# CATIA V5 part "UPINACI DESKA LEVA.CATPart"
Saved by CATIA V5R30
Part number: UPINACI DESKA LEVA
Bounding box of the stored display mesh (mm): x 0 to 36, y -273 to 273, z -173 to 173
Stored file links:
  C:\Users\ondra\Desktop\PŘÍLOHA P III\CATIA\UPINACI DESKA LEVA.CATPart
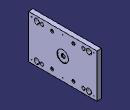
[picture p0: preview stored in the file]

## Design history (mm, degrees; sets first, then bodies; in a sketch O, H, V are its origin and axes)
Set1
  DatumSurface1 to DatumSurface37 "K12/346x"
  Plane1: type Offset, RefPlane yz-plane, Offset 36
  Plane2: type Offset, RefPlane yz-plane, Offset 36
  Sketch1 on Plane2, origin (36, 0, 0), H (0, 1, 0), V (0, 0, 1)
    point P2 (-248, -148)
    point P3 (0, -148)
    point P6 (0, 148)
    construction line L1 (-248, 148) -> (248, 148)
    construction line L2 (248, -148) -> (248, 148)
    construction line L3 (248, -148) -> (-248, -148)
    reference projected line E1 (273, 173) -> (-273, 173) from edge of DatumSurface37
    construction line L4 (0, 148) -> (0, -148)
    reference projected line E2 (273, -173) -> (-273, -173) from edge of DatumSurface33
    reference projected line E3 (273, 173) -> (273, -173) from edge of DatumSurface36
    construction line L5 (-248, -148) -> (-248, 148)
    reference projected line E4 (-273, -173) -> (-273, 173) from edge of DatumSurface34
    distance L1 E1 = 25
    distance L3 E2 = 25
    distance L2 E3 = 25
    distance L5 E4 = 25
    horizontal: L1 H, L3 H
    vertical: L2 V, L4 V, L5 V
    coincidence: P6 L1, L3 P3, L4 O
  Join1: Elements (DatumSurface1; DatumSurface2; DatumSurface3; DatumSurface4; DatumSurface5; DatumSurface6; DatumSurface7; DatumSurface8; DatumSurface9; DatumSurface10; DatumSurface11; DatumSurface12; DatumSurface13; DatumSurface14; DatumSurface15; DatumSurface16; DatumSurface17; DatumSurface18; DatumSurface19; DatumSurface20; DatumSurface21; DatumSurface22; DatumSurface23; DatumSurface24; DatumSurface25; DatumSurface26; DatumSurface27; DatumSurface28; DatumSurface29; DatumSurface30; DatumSurface31; DatumSurface32; DatumSurface33; DatumSurface34; DatumSurface35; DatumSurface36; DatumSurface37)
Body1 (main body)
  CloseSurface1: CloseElement Join1
  Sketch2 on {plane type Tangent, Support face of CloseSurface1, RefPoint Sketch1.P2}, origin (36, -248, -148), H (0, 1, 0), V (0, 0, -1)
    point P1 (0, 0)
    reference projected point E1 (0, 0) from Sketch1.P2
    coincidence: E1 P1
  Hole1: placed by Sketch2, at (36, -248, -148) direction (-1, 0, 0), diameter 4.917, depth 8, V-bottom angle 120, threaded "M6", thread diameter 6, thread depth 7, pitch 1
  UserPattern1: of Hole1, copies 6, at the points of Sketch1
  DatumPoint1
  Plane3: type Offset, RefPlane yz-plane, Offset 15
  Sketch3 on {plane type Tangent, Support face of CloseSurface1, RefPoint vertex of DatumPoint1}, origin (-3, -85, -130), H (0, 1, 0), V (0, 0, -1)
    point P1 (0, 0)
    reference projected point E1 (0, 0) from vertex of DatumPoint1
    coincidence: E1 P1
  Hole2: placed by Sketch3, at (36, -85, -130) direction (-1, 0, 0), diameter 20, through (limit type 6), counterbore diameter 24, counterbore depth 8
  DatumPoint2
  Sketch4, origin (-3, 0, 0), H (0, 1, 0), V (0, 0, -1), geometry linked from another document
  UserPattern2: of Hole2, copies 4, at the points of Sketch4
  Sketch5 on {plane type Tangent, Support face of CloseSurface1, RefPoint vertex of DatumPoint2}, origin (44.5, -39, 0), H (0, 1, 0), V (0, 0, -1)
    point P1 (0, 0)
    reference projected point E1 (0, 0) from vertex of DatumPoint2
    coincidence: E1 P1
  Hole3: placed by Sketch5, at (32, -39, 0) direction (-1, 0, 0), diameter 4.134, depth 15, V-bottom angle 120, threaded "M5", thread diameter 5, thread depth 13, pitch 0.8
  DatumPoint3
  Sketch6, origin (44.5, 0, 0), H (0, 0, -1), V (0, 1, 0), geometry linked from another document
  UserPattern3: of Hole3, copies 3, at the points of Sketch6
  Sketch7 on {plane type Tangent, Support face of CloseSurface1, RefPoint vertex of DatumPoint3}, origin (44, 0, 0), H (0, 1, 0), V (0, 0, -1)
    point P1 (0, 0)
    reference projected point E1 (0, 0) from vertex of DatumPoint3
    coincidence: E1 P1
  Hole4: placed by Sketch7, at (32, 0, 0) direction (-1, 0, 0), diameter 26, through (limit type 6), counterbore diameter 31, counterbore depth 6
